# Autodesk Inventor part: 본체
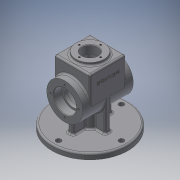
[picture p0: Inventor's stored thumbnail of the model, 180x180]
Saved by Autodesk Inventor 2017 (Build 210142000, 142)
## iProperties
Created: 2020-07
Part Number: 본체
Material: 알루미늄 6061
Document SubType Name: Modeling
Designer: mduedu
Density: 2.71 g/cm^3
Appearance: 기본값
Mass: 1025.32 g
Surface Area: 854.574 cm^2
Volume: 378.346 cm^3
Author: mduedu
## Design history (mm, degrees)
sketch "스케치1"
  geometry: C1 r 32 at (0, 0); 1 further point
  constraints: 1 centre point, 1 coincident
  dimensions: "d0" = 64 diameter of C1
extrude "돌출1" new body sketch "스케치1" stored distance "d1" = 90; taper "d2" = 0 deg
sketch "스케치3"
  geometry: L1 (0, -32)-(50, -32); L2 (50, -32)-(50, 32); L3 (50, 32)-(0, 32); L4 (0, 32)-(0, -32); C1 r 32 at (0, 0) reference; 2 further points
  constraints: 8 end point, 2 parallel, 1 coincident, 1 horizontal, 1 midpoint, 1 perpendicular, 1 tangent
  dimensions: "d5" = 50 distance of L2.end L3.end
extrude "돌출2" join sketch "스케치3" stored distance "d7" = 64; taper "d8" = 0 deg
sketch "스케치4"
  geometry: C1 r 25 at (32, 32); 1 further point
  constraints: 1 centre point, 1 coincident
  dimensions: "d9" = 50 diameter of C1
extrude "돌출3" join sketch "스케치4" distance "d10" = 5; taper "d11" = 0 deg
sketch "스케치5"
  geometry: L1 (0, -25)-(40, -25); L2 (40, -25)-(40, 25); L3 (40, 25)-(0, 25); L4 (0, 25)-(0, -25); L5 (55, -25)-(55, 25) reference; A1 r 25 centre (0, 0) between (0, 25) and (0, -25); A2 r 25 centre (0, 0) between (0, -25) and (0, 25); 2 further points
  constraints: 8 end point, 4 point on circle, 2 centre point, 2 coincident, 2 parallel, 1 horizontal, 1 midpoint, 1 perpendicular, 1 tangent
  dimensions: "d12" = 50 diameter of A1; "d13" = 15 distance between parallel lines of L2 L5
extrude "돌출4" cut sketch "스케치5" stored distance "d14" = 48; taper "d15" = 0 deg
sketch "스케치6"
  geometry: C1 r 20 at (0, 0); 1 further point
  constraints: 1 centre point, 1 coincident
  dimensions: "d16" = 40 diameter of C1
extrude "돌출5" cut sketch "스케치6" distance "d17" = 15; taper "d18" = 0 deg
sketch "스케치7"
  geometry: C1 r 17 at (0, 0); 1 further point
  constraints: 1 centre point, 1 coincident
  dimensions: "d19" = 34 diameter of C1
extrude "돌출6" cut sketch "스케치7" stored distance "d20" = 15; taper "d21" = 0 deg
fillet "모깎기1" dims "d22" = 3
fillet "모깎기2" dims "d23" = 3
fillet "모깎기3" dims "d24" = 3
fillet "모깎기4" dims "d25" = 3
fillet "모깎기5" dims "d26" = 3
sketch "스케치8"
  geometry: C1 r 14 at (0, 0); 1 further point
  constraints: 1 centre point, 1 coincident
  dimensions: "d27" = 28 diameter of C1
extrude "돌출7" cut sketch "스케치8" stored distance "d28" = 15; taper "d29" = 0 deg
node "작업 평면1"
sketch "스케치9"
  geometry: C1 r 67.5 at (0, 0); 1 further point
  constraints: 1 centre point, 1 coincident
  dimensions: "d31" = 135 diameter of C1
extrude "돌출8" join sketch "스케치9" distance "d33" = 10; taper "d34" = 0 deg
sketch "스케치10"
  geometry: C1 r 15 at (0, 0); 1 further point
  constraints: 1 centre point, 1 coincident
  dimensions: "d35" = 30 diameter of C1
extrude "돌출9" join sketch "스케치10" stored distance "d39" = 10; taper "d40" = 0 deg
sketch "스케치11"
  geometry: L1 (-35, -5)-(35, -5); L2 (35, -5)-(35, 5); L3 (35, 5)-(-35, 5); L4 (-35, 5)-(-35, -5); L5 (-35, -5)-(35, 5); L6 (35, -5)-(-35, 5); 1 further point
  constraints: 12 end point, 2 midpoint, 2 parallel, 1 horizontal, 1 perpendicular
  dimensions: "d41" = 70 distance of L3.end L2.end; "d42" = 10 distance of L2.end L1.end
extrude "돌출10" join sketch "스케치11" stored distance "d43" = 10; taper "d44" = 0 deg
sketch "스케치12"
  geometry: L1 (-5, -32)-(5, -32); L2 (5, -32)-(5, 32); L3 (5, 32)-(-5, 32); L4 (-5, 32)-(-5, -32); L5 (-5, -32)-(5, 32); L6 (5, -32)-(-5, 32); 1 further point
  constraints: 12 end point, 2 midpoint, 2 parallel, 1 horizontal, 1 perpendicular
  dimensions: "d45" = 10 distance of L3.end L2.end; "d46" = 64 distance of L2.end L1.end
extrude "돌출11" join sketch "스케치12" stored distance "d47" = 10; taper "d48" = 0 deg
fillet "모깎기6" dims "d50" = 3
fillet "모깎기7" dims "d51" = 3
sketch "스케치13" dims "d52" = 112
  geometry: 3 further points
  constraints: 2 horizontal alignment, 1 coincident, 2 other
hole "구멍1" sketch "스케치13" at (-56, 0) diameter "d54" = 9; stored, may be unused: countersink angle "d58" = 90 deg, drill point angle "d60" = 118 deg; dims "d55" = 6, "d56" = 4, "d57" = 2, "d59" = 8
fillet "모깎기8" dims "d64" = 3
sketch "스케치14" dims "d67" = 50
  geometry: 3 further points
  constraints: 2 vertical alignment, 1 coincident, 2 other
hole "구멍2" sketch "스케치14" at (0, 25) diameter "d68" = 3.242; stored, may be unused: countersink angle "d72" = 90 deg, drill point angle "d74" = 118 deg; dims "d69" = 7, "d70" = 4, "d71" = 2, "d73" = 9
sketch "스케치15" dims "d78" = 38
  geometry: 3 further points
  constraints: 2 vertical alignment, 1 coincident, 2 other
hole "구멍3" sketch "스케치15" at (0, 19) diameter "d79" = 3.242; stored, may be unused: countersink angle "d83" = 90 deg, drill point angle "d85" = 118 deg; dims "d80" = 8, "d81" = 4, "d82" = 2, "d84" = 10
fillet "모깎기9" dims "d89" = 0.3
chamfer "모따기1" distance "d90" = 1; stored, may be unused: second distance "d91" = 2, angle "d92" = 45 deg
chamfer "모따기2" distance "d93" = 1; stored, may be unused: second distance "d94" = 2, angle "d95" = 45 deg
sketch "스케치16"
  geometry: L1 (-3, 0)-(-3, -27.404) reference; L2 (54, 8)-(4, 8) reference; 2 further points
  constraints: 1 other
  dimensions: "d96" = 32 distance from line of point (29, -17) L1; "d97" = 25 distance from line of point (29, -17) L2
feature "엠보싱1" sketch "스케치16" dims "d0" = 64, "d98" = 0.5, "d99" = 0
node "솔리드1"
mirror "대칭1"
pattern_circular "원형 패턴1" dims angle "d62" = 360 deg
pattern_circular "원형 패턴2" dims angle "d76" = 360 deg
mirror "대칭2"
pattern_circular "원형 패턴3" dims angle "d87" = 360 deg
other parameters: "d30" = -65
